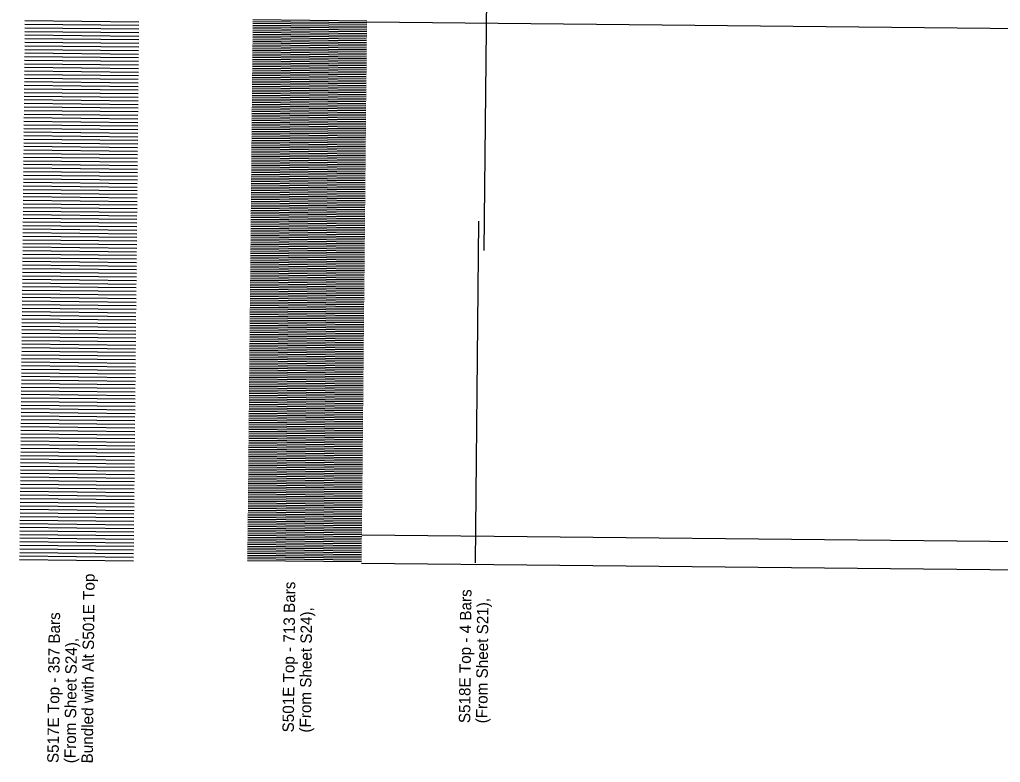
# Model space of a CAD drawing. Extents: x 632276 to 635000, y 381313 to 381846.
# Drawn here: x 634609.1 to 634781.2, y 381362.3 to 381492.7 of the extents above; entities that cross this region are included whole.
import ezdxf

# ---------------------------------------------------------------- set-up
doc = ezdxf.new("R2010")
doc.units = 0
for name, color, linetype in [('B_No_Plot', 7, 'Continuous'), ('R_Border_Scale', 7, 'Continuous'), ('R_Wall', 7, 'Continuous')]:
    doc.layers.add(name, color=color, linetype=linetype)

msp = doc.modelspace()

# ---------------------------------------------------------------- linework, layer by layer
at = {"layer": 'B_No_Plot'}
for p, q in [((634670, 381492.24), (634998.64, 381488.97)), ((634669.11, 381402.24), (634997.75, 381398.98)), ((634669.06, 381397.25), (634997.7, 381393.98))]:
    msp.add_line(p, q, dxfattribs=at)
at = {"layer": 'R_Border_Scale'}
for p, q in [((634690.61, 381452.12), (634691.2, 381512.11)), ((634629.99, 381490.97), (634609.99, 381491.17)), ((634630, 381492.23), (634610, 381492.43)), ((634630, 381491.6), (634610, 381491.8)), ((634669.99, 381491.14), (634649.99, 381491.34)), ((634669.99, 381490.82), (634649.99, 381491.02)), ((634670, 381492.08), (634650, 381492.28)), ((634670, 381491.77), (634650, 381491.97)), ((634670, 381491.45), (634650, 381491.65)), ((634670.01, 381492.4), (634650.01, 381492.6)), ((634629.97, 381489.08), (634609.97, 381489.28)), ((634629.98, 381490.34), (634609.98, 381490.54)), ((634629.98, 381489.71), (634609.98, 381489.91)), ((634669.98, 381489.88), (634649.98, 381490.07)), ((634669.98, 381489.56), (634649.98, 381489.76)), ((634669.97, 381489.25), (634649.98, 381489.44)), ((634669.99, 381490.51), (634649.99, 381490.71)), ((634669.98, 381490.19), (634649.99, 381490.39)), ((634629.96, 381487.82), (634609.96, 381488.02)), ((634629.96, 381488.45), (634609.97, 381488.65)), ((634669.96, 381487.98), (634649.96, 381488.18)), ((634669.96, 381487.67), (634649.96, 381487.87)), ((634669.96, 381487.35), (634649.96, 381487.55)), ((634669.97, 381488.93), (634649.97, 381489.13)), ((634669.97, 381488.61), (634649.97, 381488.81)), ((634669.97, 381488.3), (634649.97, 381488.5)), ((634629.94, 381485.92), (634609.94, 381486.12)), ((634629.95, 381487.19), (634609.95, 381487.38)), ((634629.95, 381486.56), (634609.95, 381486.75)), ((634669.94, 381486.09), (634649.94, 381486.29)), ((634669.94, 381485.78), (634649.94, 381485.98)), ((634669.95, 381487.04), (634649.95, 381487.24)), ((634669.95, 381486.72), (634649.95, 381486.92)), ((634669.95, 381486.41), (634649.95, 381486.61)), ((634629.92, 381484.03), (634609.92, 381484.23)), ((634629.93, 381485.29), (634609.93, 381485.49)), ((634629.93, 381484.66), (634609.93, 381484.86)), ((634669.92, 381483.89), (634649.92, 381484.08)), ((634669.93, 381485.15), (634649.93, 381485.35)), ((634669.93, 381484.83), (634649.93, 381485.03)), ((634669.93, 381484.52), (634649.93, 381484.71)), ((634669.92, 381484.2), (634649.93, 381484.4)), ((634669.94, 381485.46), (634649.94, 381485.66)), ((634629.91, 381482.77), (634609.91, 381482.97)), ((634629.91, 381483.4), (634609.92, 381483.6)), ((634669.91, 381482.94), (634649.91, 381483.14)), ((634669.91, 381482.62), (634649.91, 381482.82)), ((634669.91, 381482.31), (634649.91, 381482.51)), ((634669.92, 381483.57), (634649.92, 381483.77)), ((634669.92, 381483.25), (634649.92, 381483.45)), ((634629.89, 381480.88), (634609.89, 381481.08)), ((634629.9, 381482.14), (634609.9, 381482.34)), ((634629.9, 381481.51), (634609.9, 381481.71)), ((634669.89, 381481.05), (634649.89, 381481.25)), ((634669.89, 381480.73), (634649.89, 381480.93)), ((634669.9, 381481.99), (634649.9, 381482.19)), ((634669.9, 381481.68), (634649.9, 381481.88)), ((634669.9, 381481.36), (634649.9, 381481.56)), ((634629.87, 381478.99), (634609.87, 381479.19)), ((634629.88, 381480.25), (634609.88, 381480.45)), ((634629.88, 381479.62), (634609.88, 381479.82)), ((634669.87, 381478.84), (634649.87, 381479.04)), ((634669.88, 381480.1), (634649.88, 381480.3)), ((634669.88, 381479.79), (634649.88, 381479.99)), ((634669.88, 381479.47), (634649.88, 381479.67)), ((634669.87, 381479.16), (634649.88, 381479.35)), ((634669.89, 381480.42), (634649.89, 381480.62)), ((634629.85, 381477.1), (634609.85, 381477.3)), ((634629.86, 381477.73), (634609.86, 381477.93)), ((634629.86, 381478.36), (634609.87, 381478.56)), ((634669.86, 381477.89), (634649.86, 381478.09)), ((634669.86, 381477.58), (634649.86, 381477.78)), ((634669.86, 381477.26), (634649.86, 381477.46)), ((634669.87, 381478.53), (634649.87, 381478.72)), ((634669.86, 381478.21), (634649.87, 381478.41)), ((634629.84, 381475.84), (634609.84, 381476.03)), ((634629.85, 381476.47), (634609.85, 381476.66)), ((634669.84, 381476), (634649.84, 381476.2)), ((634669.84, 381475.69), (634649.84, 381475.89)), ((634669.84, 381475.37), (634649.84, 381475.57)), ((634669.85, 381476.95), (634649.85, 381477.15)), ((634669.85, 381476.63), (634649.85, 381476.83)), ((634669.85, 381476.32), (634649.85, 381476.52)), ((634629.82, 381473.94), (634609.82, 381474.14)), ((634629.83, 381475.2), (634609.83, 381475.4)), ((634629.83, 381474.57), (634609.83, 381474.77)), ((634669.82, 381473.8), (634649.82, 381473.99)), ((634669.83, 381475.06), (634649.83, 381475.26)), ((634669.83, 381474.74), (634649.83, 381474.94)), ((634669.83, 381474.43), (634649.83, 381474.63)), ((634669.82, 381474.11), (634649.83, 381474.31)), ((634629.8, 381472.05), (634609.8, 381472.25)), ((634629.81, 381472.68), (634609.81, 381472.88)), ((634629.81, 381473.31), (634609.82, 381473.51)), ((634669.8, 381471.9), (634649.8, 381472.1)), ((634669.81, 381472.85), (634649.81, 381473.05)), ((634669.81, 381472.53), (634649.81, 381472.73)), ((634669.81, 381472.22), (634649.81, 381472.42)), ((634669.82, 381473.48), (634649.82, 381473.68)), ((634669.81, 381473.17), (634649.82, 381473.36)), ((634629.78, 381470.16), (634609.78, 381470.36)), ((634629.79, 381470.79), (634609.79, 381470.99)), ((634629.8, 381471.42), (634609.8, 381471.62)), ((634669.79, 381470.96), (634649.79, 381471.16)), ((634669.79, 381470.64), (634649.79, 381470.84)), ((634669.79, 381470.33), (634649.79, 381470.53)), ((634669.8, 381471.59), (634649.8, 381471.79)), ((634669.8, 381471.27), (634649.8, 381471.47)), ((634629.77, 381468.9), (634609.77, 381469.1)), ((634629.78, 381469.53), (634609.78, 381469.73)), ((634669.77, 381468.75), (634649.77, 381468.95)), ((634669.77, 381468.44), (634649.77, 381468.63)), ((634669.78, 381470.01), (634649.78, 381470.21)), ((634669.78, 381469.7), (634649.78, 381469.9)), ((634669.78, 381469.38), (634649.78, 381469.58)), ((634669.77, 381469.07), (634649.78, 381469.27)), ((634629.75, 381467.01), (634609.75, 381467.21)), ((634629.76, 381467.64), (634609.76, 381467.84)), ((634629.76, 381468.27), (634609.77, 381468.47)), ((634669.75, 381466.86), (634649.75, 381467.06)), ((634669.76, 381467.81), (634649.76, 381468)), ((634669.76, 381467.49), (634649.76, 381467.69)), ((634669.76, 381467.17), (634649.76, 381467.37)), ((634669.76, 381468.12), (634649.77, 381468.32)), ((634629.73, 381465.12), (634609.73, 381465.31)), ((634629.74, 381465.75), (634609.74, 381465.94)), ((634629.75, 381466.38), (634609.75, 381466.58)), ((634669.73, 381464.97), (634649.73, 381465.17)), ((634669.74, 381465.91), (634649.74, 381466.11)), ((634669.74, 381465.6), (634649.74, 381465.8)), ((634669.74, 381465.28), (634649.74, 381465.48)), ((634669.75, 381466.54), (634649.75, 381466.74)), ((634669.75, 381466.23), (634649.75, 381466.43)), ((634629.71, 381463.22), (634609.71, 381463.42)), ((634629.72, 381463.85), (634609.72, 381464.05)), ((634629.73, 381464.48), (634609.73, 381464.68)), ((634669.72, 381464.02), (634649.72, 381464.22)), ((634669.72, 381463.71), (634649.72, 381463.91)), ((634669.72, 381463.39), (634649.72, 381463.59)), ((634669.73, 381464.65), (634649.73, 381464.85)), ((634669.73, 381464.34), (634649.73, 381464.54)), ((634629.7, 381461.96), (634609.7, 381462.16)), ((634629.71, 381462.59), (634609.71, 381462.79)), ((634669.7, 381461.81), (634649.7, 381462.01)), ((634669.7, 381461.5), (634649.7, 381461.7)), ((634669.71, 381462.76), (634649.71, 381462.96)), ((634669.71, 381462.45), (634649.71, 381462.64)), ((634669.71, 381462.13), (634649.71, 381462.33)), ((634669.71, 381463.08), (634649.72, 381463.27)), ((634629.68, 381460.07), (634609.68, 381460.27)), ((634629.69, 381460.7), (634609.69, 381460.9)), ((634629.7, 381461.33), (634609.7, 381461.53)), ((634669.68, 381459.92), (634649.68, 381460.12)), ((634669.69, 381460.87), (634649.69, 381461.07)), ((634669.69, 381460.55), (634649.69, 381460.75)), ((634669.69, 381460.24), (634649.69, 381460.44)), ((634669.7, 381461.18), (634649.7, 381461.38)), ((634629.66, 381458.18), (634609.66, 381458.38)), ((634629.67, 381458.81), (634609.67, 381459.01)), ((634629.68, 381459.44), (634609.68, 381459.64)), ((634669.67, 381458.98), (634649.67, 381459.18)), ((634669.67, 381458.66), (634649.67, 381458.86)), ((634669.67, 381458.35), (634649.67, 381458.55)), ((634669.68, 381459.61), (634649.68, 381459.81)), ((634669.68, 381459.29), (634649.68, 381459.49)), ((634629.65, 381456.92), (634609.65, 381457.12)), ((634629.66, 381457.55), (634609.66, 381457.75)), ((634669.65, 381456.77), (634649.65, 381456.97)), ((634669.65, 381456.45), (634649.65, 381456.65)), ((634669.66, 381457.72), (634649.66, 381457.91)), ((634669.66, 381457.4), (634649.66, 381457.6)), ((634669.65, 381457.09), (634649.66, 381457.28)), ((634669.66, 381458.03), (634649.67, 381458.23)), ((634689.06, 381397.3), (634689.66, 381457.29)), ((634629.63, 381455.03), (634609.63, 381455.22)), ((634629.64, 381455.66), (634609.64, 381455.86)), ((634629.65, 381456.29), (634609.65, 381456.49)), ((634669.63, 381454.88), (634649.63, 381455.08)), ((634669.64, 381455.82), (634649.64, 381456.02)), ((634669.64, 381455.51), (634649.64, 381455.71)), ((634669.64, 381455.19), (634649.64, 381455.39)), ((634669.65, 381456.14), (634649.65, 381456.34)), ((634629.61, 381453.13), (634609.61, 381453.33)), ((634629.62, 381453.76), (634609.62, 381453.96)), ((634629.63, 381454.4), (634609.63, 381454.59)), ((634669.62, 381453.93), (634649.62, 381454.13)), ((634669.62, 381453.62), (634649.62, 381453.82)), ((634669.62, 381453.3), (634649.62, 381453.5)), ((634669.61, 381452.99), (634649.62, 381453.19)), ((634669.63, 381454.56), (634649.63, 381454.76)), ((634669.63, 381454.25), (634649.63, 381454.45)), ((634629.6, 381451.87), (634609.6, 381452.07)), ((634629.59, 381451.24), (634609.6, 381451.44)), ((634629.61, 381452.5), (634609.61, 381452.7)), ((634669.6, 381451.73), (634649.6, 381451.92)), ((634669.6, 381451.41), (634649.6, 381451.61)), ((634669.61, 381452.67), (634649.61, 381452.87)), ((634669.61, 381452.36), (634649.61, 381452.55)), ((634669.6, 381452.04), (634649.61, 381452.24)), ((634629.58, 381449.98), (634609.58, 381450.18)), ((634629.59, 381450.61), (634609.59, 381450.81)), ((634669.58, 381449.83), (634649.58, 381450.03)), ((634669.58, 381449.52), (634649.58, 381449.72)), ((634669.59, 381450.78), (634649.59, 381450.98)), ((634669.59, 381450.46), (634649.59, 381450.66)), ((634669.59, 381450.15), (634649.59, 381450.35)), ((634669.6, 381451.09), (634649.6, 381451.29)), ((634629.56, 381448.09), (634609.56, 381448.29)), ((634629.57, 381448.72), (634609.57, 381448.92)), ((634629.58, 381449.35), (634609.58, 381449.55)), ((634669.57, 381448.89), (634649.57, 381449.09)), ((634669.57, 381448.57), (634649.57, 381448.77)), ((634669.57, 381448.26), (634649.57, 381448.46)), ((634669.56, 381447.94), (634649.57, 381448.14)), ((634669.58, 381449.2), (634649.58, 381449.4)), ((634629.55, 381446.83), (634609.55, 381447.03)), ((634629.54, 381446.2), (634609.55, 381446.4)), ((634629.56, 381447.46), (634609.56, 381447.66)), ((634669.55, 381446.68), (634649.55, 381446.88)), ((634669.55, 381446.37), (634649.55, 381446.56)), ((634669.55, 381446.05), (634649.55, 381446.25)), ((634669.56, 381447.63), (634649.56, 381447.83)), ((634669.56, 381447.31), (634649.56, 381447.51)), ((634669.55, 381447), (634649.56, 381447.19)), ((634629.53, 381444.94), (634609.53, 381445.14)), ((634629.53, 381444.31), (634609.53, 381444.5)), ((634629.54, 381445.57), (634609.54, 381445.77)), ((634669.53, 381444.79), (634649.53, 381444.99)), ((634669.53, 381444.47), (634649.53, 381444.67)), ((634669.54, 381445.73), (634649.54, 381445.93)), ((634669.54, 381445.42), (634649.54, 381445.62)), ((634669.54, 381445.1), (634649.54, 381445.3)), ((634629.51, 381443.04), (634609.51, 381443.24)), ((634629.52, 381443.68), (634609.52, 381443.87)), ((634669.51, 381442.9), (634649.51, 381443.1)), ((634669.51, 381442.58), (634649.51, 381442.78)), ((634669.52, 381443.84), (634649.52, 381444.04)), ((634669.52, 381443.53), (634649.52, 381443.73)), ((634669.52, 381443.21), (634649.52, 381443.41)), ((634669.53, 381444.16), (634649.53, 381444.36)), ((634629.5, 381441.78), (634609.5, 381441.98)), ((634629.49, 381441.15), (634609.5, 381441.35)), ((634629.51, 381442.41), (634609.51, 381442.61)), ((634669.5, 381441.64), (634649.5, 381441.83)), ((634669.5, 381441.32), (634649.5, 381441.52)), ((634669.5, 381441.01), (634649.5, 381441.2)), ((634669.51, 381442.27), (634649.51, 381442.47)), ((634669.5, 381441.95), (634649.51, 381442.15)), ((634629.48, 381439.89), (634609.48, 381440.09)), ((634629.48, 381439.26), (634609.48, 381439.46)), ((634629.49, 381440.52), (634609.49, 381440.72)), ((634669.48, 381439.74), (634649.48, 381439.94)), ((634669.48, 381439.43), (634649.48, 381439.63)), ((634669.49, 381440.69), (634649.49, 381440.89)), ((634669.49, 381440.37), (634649.49, 381440.57)), ((634669.49, 381440.06), (634649.49, 381440.26)), ((634629.46, 381438), (634609.46, 381438.2)), ((634629.47, 381438.63), (634609.47, 381438.83)), ((634669.46, 381437.85), (634649.46, 381438.05)), ((634669.46, 381437.54), (634649.46, 381437.74)), ((634669.47, 381438.8), (634649.47, 381439)), ((634669.47, 381438.48), (634649.47, 381438.68)), ((634669.47, 381438.17), (634649.47, 381438.37)), ((634669.48, 381439.11), (634649.48, 381439.31)), ((634629.45, 381436.74), (634609.45, 381436.94)), ((634629.44, 381436.11), (634609.45, 381436.31)), ((634629.46, 381437.37), (634609.46, 381437.57)), ((634669.45, 381436.59), (634649.45, 381436.79)), ((634669.45, 381436.28), (634649.45, 381436.47)), ((634669.44, 381435.96), (634649.45, 381436.16)), ((634669.46, 381437.22), (634649.46, 381437.42)), ((634669.45, 381436.91), (634649.46, 381437.11)), ((634629.43, 381434.85), (634609.43, 381435.05)), ((634629.43, 381434.22), (634609.43, 381434.42)), ((634629.44, 381435.48), (634609.44, 381435.68)), ((634669.43, 381434.7), (634649.43, 381434.9)), ((634669.43, 381434.38), (634649.43, 381434.58)), ((634669.43, 381434.07), (634649.43, 381434.27)), ((634669.44, 381435.65), (634649.44, 381435.84)), ((634669.44, 381435.33), (634649.44, 381435.53)), ((634669.44, 381435.01), (634649.44, 381435.21)), ((634629.41, 381432.96), (634609.41, 381433.15)), ((634629.41, 381432.32), (634609.41, 381432.52)), ((634629.42, 381433.59), (634609.42, 381433.78)), ((634669.41, 381432.81), (634649.41, 381433.01)), ((634669.41, 381432.49), (634649.41, 381432.69)), ((634669.42, 381433.75), (634649.42, 381433.95)), ((634669.42, 381433.44), (634649.42, 381433.64)), ((634669.42, 381433.12), (634649.42, 381433.32)), ((634629.4, 381431.69), (634609.4, 381431.89)), ((634629.39, 381431.06), (634609.4, 381431.26)), ((634669.39, 381430.6), (634649.39, 381430.8)), ((634669.4, 381431.55), (634649.4, 381431.75)), ((634669.4, 381431.23), (634649.4, 381431.43)), ((634669.39, 381430.92), (634649.4, 381431.11)), ((634669.41, 381432.18), (634649.41, 381432.38)), ((634669.4, 381431.86), (634649.41, 381432.06)), ((634629.38, 381429.8), (634609.38, 381430)), ((634629.38, 381429.17), (634609.38, 381429.37)), ((634629.39, 381430.43), (634609.39, 381430.63)), ((634669.38, 381429.65), (634649.38, 381429.85)), ((634669.38, 381429.34), (634649.38, 381429.54)), ((634669.38, 381429.02), (634649.38, 381429.22)), ((634669.39, 381430.29), (634649.39, 381430.48)), ((634669.39, 381429.97), (634649.39, 381430.17)), ((634629.36, 381427.91), (634609.36, 381428.11)), ((634629.36, 381427.28), (634609.36, 381427.48)), ((634629.37, 381428.54), (634609.37, 381428.74)), ((634669.36, 381427.76), (634649.36, 381427.96)), ((634669.36, 381427.45), (634649.36, 381427.65)), ((634669.36, 381427.13), (634649.36, 381427.33)), ((634669.37, 381428.71), (634649.37, 381428.91)), ((634669.37, 381428.39), (634649.37, 381428.59)), ((634669.37, 381428.08), (634649.37, 381428.28)), ((634629.34, 381425.39), (634609.34, 381425.59)), ((634629.35, 381426.65), (634609.35, 381426.85)), ((634629.34, 381426.02), (634609.35, 381426.22)), ((634669.34, 381425.56), (634649.34, 381425.75)), ((634669.35, 381426.82), (634649.35, 381427.02)), ((634669.35, 381426.5), (634649.35, 381426.7)), ((634669.35, 381426.19), (634649.35, 381426.39)), ((634669.34, 381425.87), (634649.35, 381426.07)), ((634629.33, 381424.76), (634609.33, 381424.96)), ((634629.33, 381424.13), (634609.33, 381424.33)), ((634669.32, 381423.66), (634649.32, 381423.86)), ((634669.33, 381424.61), (634649.33, 381424.81)), ((634669.33, 381424.29), (634649.33, 381424.49)), ((634669.33, 381423.98), (634649.33, 381424.18)), ((634669.34, 381425.24), (634649.34, 381425.44)), ((634669.34, 381424.93), (634649.34, 381425.12)), ((634629.31, 381422.87), (634609.31, 381423.07)), ((634629.31, 381422.24), (634609.31, 381422.43)), ((634629.32, 381423.5), (634609.32, 381423.7)), ((634669.31, 381422.72), (634649.31, 381422.92)), ((634669.31, 381422.4), (634649.31, 381422.6)), ((634669.31, 381422.09), (634649.31, 381422.29)), ((634669.32, 381423.35), (634649.32, 381423.55)), ((634669.32, 381423.03), (634649.32, 381423.23)), ((634629.29, 381420.97), (634609.29, 381421.17)), ((634629.29, 381420.34), (634609.29, 381420.54)), ((634629.3, 381421.61), (634609.3, 381421.8)), ((634669.29, 381420.51), (634649.29, 381420.71)), ((634669.29, 381420.2), (634649.29, 381420.39)), ((634669.3, 381421.77), (634649.3, 381421.97)), ((634669.3, 381421.46), (634649.3, 381421.66)), ((634669.3, 381421.14), (634649.3, 381421.34)), ((634669.29, 381420.83), (634649.3, 381421.03)), ((634629.28, 381419.71), (634609.28, 381419.91)), ((634629.28, 381419.08), (634609.28, 381419.28)), ((634669.27, 381418.62), (634649.27, 381418.82)), ((634669.28, 381419.57), (634649.28, 381419.76)), ((634669.28, 381419.25), (634649.28, 381419.45)), ((634669.28, 381418.93), (634649.28, 381419.13)), ((634669.29, 381419.88), (634649.29, 381420.08)), ((634629.26, 381417.82), (634609.26, 381418.02)), ((634629.26, 381417.19), (634609.26, 381417.39)), ((634629.27, 381418.45), (634609.27, 381418.65)), ((634669.26, 381417.67), (634649.26, 381417.87)), ((634669.26, 381417.36), (634649.26, 381417.56)), ((634669.26, 381417.04), (634649.26, 381417.24)), ((634669.27, 381418.3), (634649.27, 381418.5)), ((634669.27, 381417.99), (634649.27, 381418.19)), ((634629.24, 381415.93), (634609.24, 381416.13)), ((634629.24, 381415.3), (634609.24, 381415.5)), ((634629.25, 381416.56), (634609.25, 381416.76)), ((634669.24, 381415.47), (634649.24, 381415.67)), ((634669.24, 381415.15), (634649.24, 381415.35)), ((634669.25, 381416.73), (634649.25, 381416.93)), ((634669.25, 381416.41), (634649.25, 381416.61)), ((634669.25, 381416.1), (634649.25, 381416.3)), ((634669.24, 381415.78), (634649.25, 381415.98)), ((634629.22, 381413.41), (634609.22, 381413.61)), ((634629.23, 381414.67), (634609.23, 381414.87)), ((634629.22, 381414.04), (634609.23, 381414.24)), ((634669.22, 381413.57), (634649.22, 381413.77)), ((634669.23, 381414.52), (634649.23, 381414.72)), ((634669.23, 381414.21), (634649.23, 381414.4)), ((634669.23, 381413.89), (634649.23, 381414.09)), ((634669.23, 381414.84), (634649.24, 381415.03)), ((634629.21, 381412.78), (634609.21, 381412.98)), ((634629.21, 381412.15), (634609.21, 381412.35)), ((634669.2, 381411.68), (634649.2, 381411.88)), ((634669.21, 381412.63), (634649.21, 381412.83)), ((634669.21, 381412.31), (634649.21, 381412.51)), ((634669.21, 381412), (634649.21, 381412.2)), ((634669.22, 381413.26), (634649.22, 381413.46)), ((634669.22, 381412.94), (634649.22, 381413.14)), ((634629.19, 381410.89), (634609.19, 381411.08)), ((634629.19, 381410.25), (634609.19, 381410.45)), ((634629.2, 381411.52), (634609.2, 381411.71)), ((634669.19, 381410.42), (634649.19, 381410.62)), ((634669.19, 381410.11), (634649.19, 381410.31)), ((634669.2, 381411.37), (634649.2, 381411.57)), ((634669.2, 381411.05), (634649.2, 381411.25)), ((634669.19, 381410.74), (634649.2, 381410.94)), ((634629.17, 381408.36), (634609.17, 381408.56)), ((634629.18, 381409.62), (634609.18, 381409.82)), ((634629.17, 381408.99), (634609.18, 381409.19)), ((634669.17, 381408.53), (634649.17, 381408.73)), ((634669.17, 381408.21), (634649.17, 381408.41)), ((634669.18, 381409.48), (634649.18, 381409.68)), ((634669.18, 381409.16), (634649.18, 381409.36)), ((634669.18, 381408.85), (634649.18, 381409.04)), ((634669.18, 381409.79), (634649.19, 381409.99)), ((634629.15, 381406.47), (634609.15, 381406.67)), ((634629.16, 381407.73), (634609.16, 381407.93)), ((634629.16, 381407.1), (634609.16, 381407.3)), ((634669.15, 381406.64), (634649.15, 381406.84)), ((634669.16, 381407.58), (634649.16, 381407.78)), ((634669.16, 381407.27), (634649.16, 381407.47)), ((634669.16, 381406.95), (634649.16, 381407.15)), ((634669.17, 381407.9), (634649.17, 381408.1)), ((634629.14, 381405.84), (634609.14, 381406.04)), ((634629.14, 381405.21), (634609.14, 381405.41)), ((634669.14, 381405.69), (634649.14, 381405.89)), ((634669.14, 381405.38), (634649.14, 381405.58)), ((634669.14, 381405.06), (634649.14, 381405.26)), ((634669.13, 381404.75), (634649.14, 381404.95)), ((634669.15, 381406.32), (634649.15, 381406.52)), ((634669.15, 381406.01), (634649.15, 381406.21)), ((634629.12, 381403.32), (634609.12, 381403.52)), ((634629.13, 381404.58), (634609.13, 381404.78)), ((634629.12, 381403.95), (634609.13, 381404.15)), ((634669.12, 381403.49), (634649.12, 381403.68)), ((634669.12, 381403.17), (634649.12, 381403.37)), ((634669.13, 381404.43), (634649.13, 381404.63)), ((634669.13, 381404.12), (634649.13, 381404.32)), ((634669.13, 381403.8), (634649.13, 381404)), ((634629.1, 381401.43), (634609.1, 381401.63)), ((634629.11, 381402.69), (634609.11, 381402.89)), ((634629.11, 381402.06), (634609.11, 381402.26)), ((634669.1, 381401.59), (634649.1, 381401.79)), ((634669.1, 381401.28), (634649.1, 381401.48)), ((634669.11, 381402.54), (634649.11, 381402.74)), ((634669.11, 381402.22), (634649.11, 381402.42)), ((634669.11, 381401.91), (634649.11, 381402.11)), ((634669.12, 381402.86), (634649.12, 381403.05)), ((634629.08, 381399.53), (634609.08, 381399.73)), ((634629.09, 381400.8), (634609.09, 381400.99)), ((634629.09, 381400.17), (634609.09, 381400.36)), ((634669.09, 381400.65), (634649.09, 381400.85)), ((634669.09, 381400.33), (634649.09, 381400.53)), ((634669.09, 381400.02), (634649.09, 381400.22)), ((634669.08, 381399.7), (634649.09, 381399.9)), ((634669.1, 381400.96), (634649.1, 381401.16)), ((634629.07, 381398.27), (634609.07, 381398.47)), ((634629.07, 381398.9), (634609.08, 381399.1)), ((634669.07, 381398.44), (634649.07, 381398.64)), ((634669.07, 381398.13), (634649.07, 381398.32)), ((634669.07, 381397.81), (634649.07, 381398.01)), ((634669.08, 381399.39), (634649.08, 381399.59)), ((634669.08, 381399.07), (634649.08, 381399.27)), ((634669.07, 381398.76), (634649.08, 381398.96)), ((634629.06, 381397.64), (634609.06, 381397.84)), ((634669.06, 381397.5), (634649.06, 381397.69))]:
    msp.add_line(p, q, dxfattribs=at)

# ---------------------------------------------------------------- texts
at = {"layer": 'R_Wall'}
for s, p in [('Bundled with Alt S501E Top', (634621.91, 381362.12)), ('S501E Top - 713 Bars', (634657.19, 381367.56)), ('S518E Top - 4 Bars', (634688.15, 381369.19)), ('(From Sheet S21), ', (634691.15, 381369.16)), ('S517E Top - 357 Bars', (634615.91, 381362.18)), ('(From Sheet S24),', (634660.19, 381367.53)), ('(From Sheet S24),', (634618.91, 381362.15))]:
    msp.add_text(s, height=2, rotation=89.4304, dxfattribs=at).set_placement(p)

doc.saveas('drawing.dxf')
